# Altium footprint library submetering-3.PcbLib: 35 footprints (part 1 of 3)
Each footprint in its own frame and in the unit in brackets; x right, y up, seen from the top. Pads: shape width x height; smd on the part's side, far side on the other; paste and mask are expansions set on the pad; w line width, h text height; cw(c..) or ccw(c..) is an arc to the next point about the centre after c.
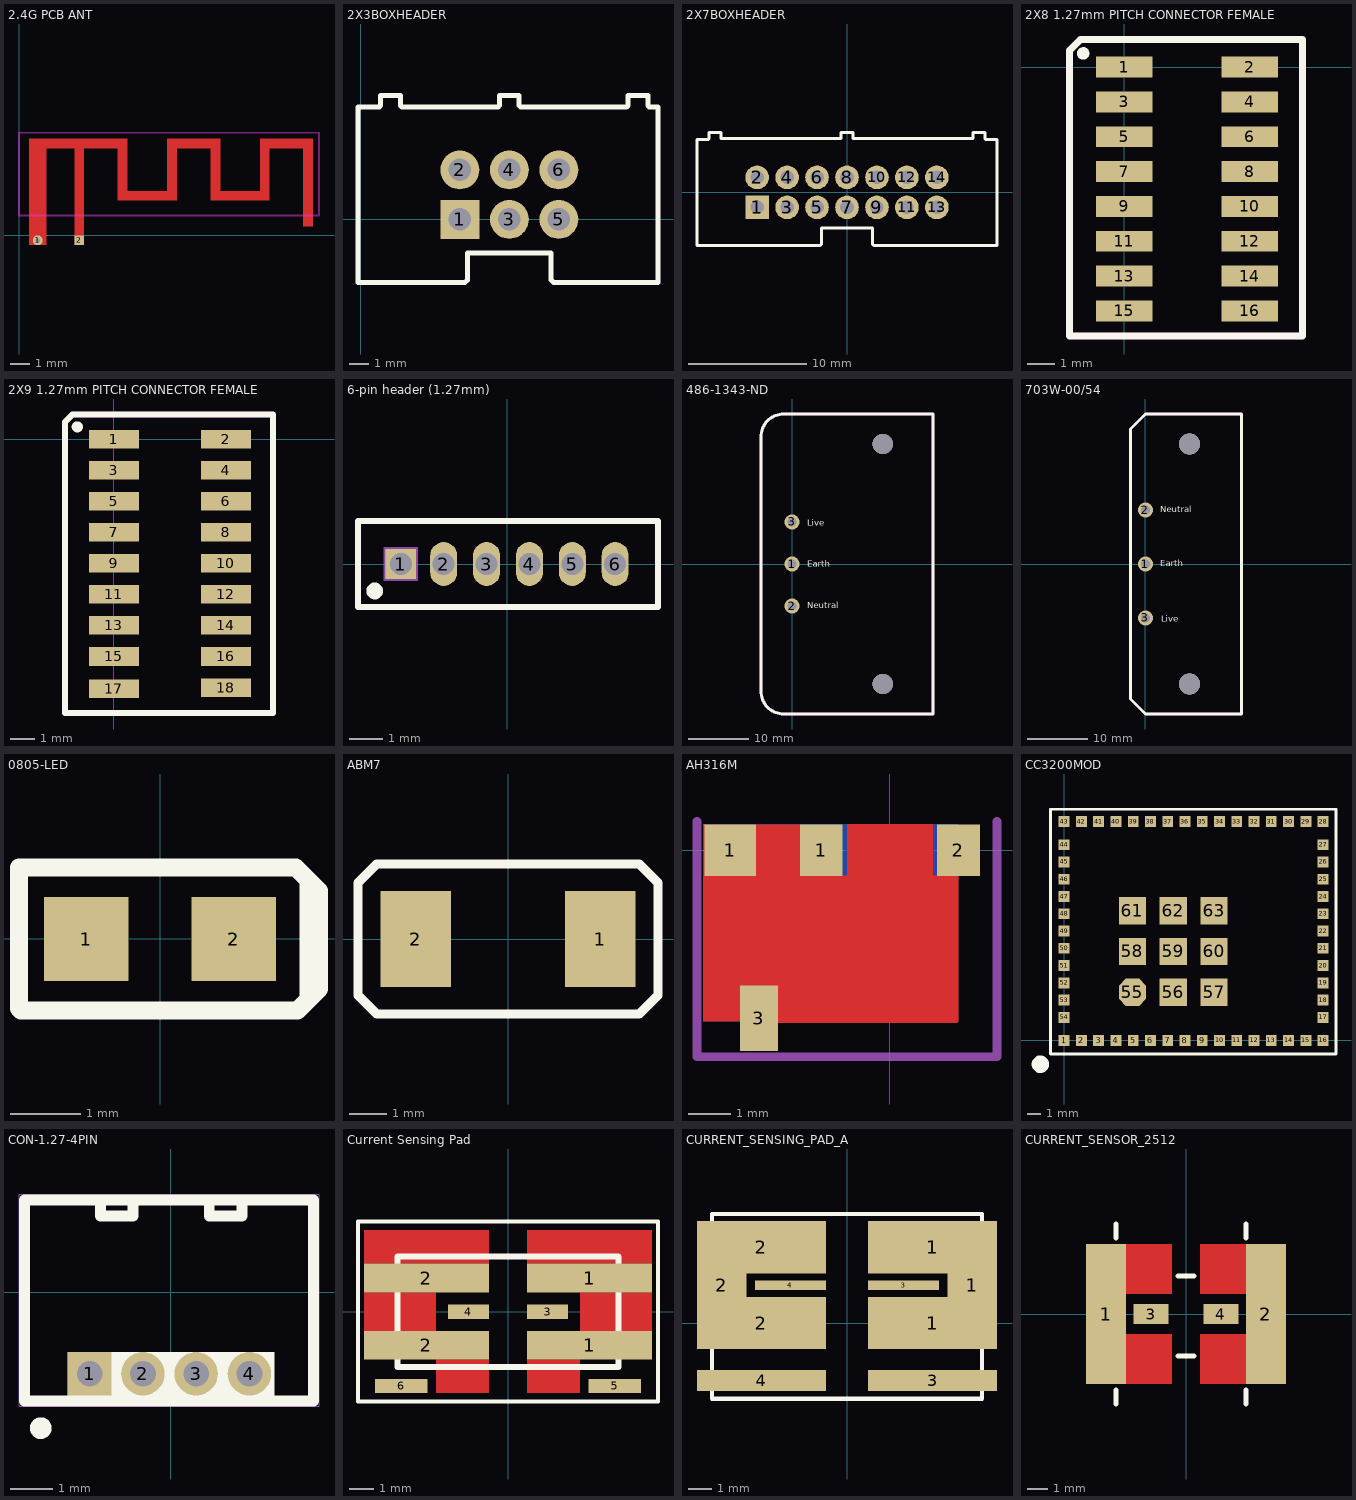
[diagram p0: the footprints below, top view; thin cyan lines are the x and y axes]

## 2.4G PCB ANT [mm] "2.4G PCb Single Ended Antenna"
pads (2):
  round 0.5 hole 0.25 paste+0 mask+0: 1(0.95,-0.25)
  rect 0.5x0.5 smd paste+0 mask+0: 2(3.05,-0.25)
TopLayer:
  rectangle: 14.4,0.46 14.9,4.4
  rectangle: 12.2,4.4 14.9,4.9
  rectangle: 12.2,1.76 12.7,4.4
  rectangle: 10.2,1.76 12.2,2.26
  rectangle: 9.7,1.76 10.2,4.4
  rectangle: 7.5,4.4 10.2,4.9
  rectangle: 7.5,1.76 8,4.4
  rectangle: 5.5,1.76 7.5,2.26
  rectangle: 5,1.76 5.5,4.4
  rectangle: 2.8,-0.5 3.3,4.4
  rectangle: 0.5,-0.5 1.4,4.4
  rectangle: 0.5,4.4 5.5,4.9
KeepOutLayer:
  lines w0.1: 0,1 15.2,1 15.2,5.2 0,5.2 0,1

## 2X3BOXHEADER [mm]
pads (6):
  rect 2x2 hole 1.15: 1(5.08,0)
  round 2 hole 1.15: 2(5.08,2.54) 3(7.62,0) 4(7.62,2.54) 5(10.16,0) 6(10.16,2.54)
TopOverlay:
  lines w0.254: -0.15,-3.23 5.352,-3.23 5.47,-3.112 5.47,-1.73 9.77,-1.73 9.77,-3.112 9.888,-3.23 15.255,-3.23 15.255,5.77 14.804,5.77 14.732,5.842 14.732,6.35 13.716,6.35 13.716,5.842 13.644,5.77 8.2,5.77 8.128,5.842 8.128,6.35 7.112,6.35 7.112,5.842 7.04,5.77 2.104,5.77 2.032,5.842 2.032,6.35 1.016,6.35 1.016,5.842 0.944,5.77 -0.15,5.77 -0.15,-3.23

## 2X7BOXHEADER [mm]
pads (14):
  rect 2x2 hole 1.15: 1(-7.62,-1.27)
  round 2 hole 1.15: 2(-7.62,1.27) 3(-5.08,-1.27) 4(-5.08,1.27) 5(-2.54,-1.27) 6(-2.54,1.27) 7(0,-1.27) 8(0,1.27) 9(2.54,-1.27) 10(2.54,1.27) 11(5.08,-1.27) 12(5.08,1.27) 13(7.62,-1.27) 14(7.62,1.27)
TopOverlay:
  lines w0.254: -12.715,-4.5 -2.268,-4.5 -2.15,-4.382 -2.15,-3 2.15,-3 2.15,-4.382 2.268,-4.5 12.715,-4.5 12.715,4.5 11.756,4.5 11.684,4.572 11.684,5.08 10.668,5.08 10.668,4.572 0.508,4.572 0.508,5.08 -0.508,5.08 -0.508,4.572 -10.668,4.572 -10.668,5.08 -11.684,5.08 -11.684,4.572 -11.756,4.5 -12.715,4.5 -12.715,-4.5

## 2X8 1.27mm PITCH CONNECTOR FEMALE [mm] "2X8 1.27mm PITCH CONNECTOR FEMALE"
pads (16):
  rect 2.05x0.76 smd: 1(0,0) 2(4.575,0) 3(0,-1.27) 4(4.575,-1.27) 5(0,-2.54) 6(4.575,-2.54) 7(0,-3.81) 8(4.575,-3.81) 9(0,-5.08) 10(4.575,-5.08) 11(0,-6.35) 12(4.575,-6.35) 13(0,-7.62) 14(4.575,-7.62) 15(0,-8.89) 16(4.575,-8.89)
TopOverlay:
  circle w0.254: c-1.5,0.5 r0.1
TopOverlay keep-out:
  lines w0.254: -2,-9.8 6.5,-9.8 6.5,1 -1.6,1 -2,0.6 -2,-9.8

## 2X9 1.27mm PITCH CONNECTOR FEMALE [mm] "2X9 1.27mm PITCH CONNECTOR FEMALE"
pads (18):
  rect 2.05x0.76 smd: 1(0,0) 2(4.575,0) 3(0,-1.27) 4(4.575,-1.27) 5(0,-2.54) 6(4.575,-2.54) 7(0,-3.81) 8(4.575,-3.81) 9(0,-5.08) 10(4.575,-5.08) 11(0,-6.35) 12(4.575,-6.35) 13(0,-7.62) 14(4.575,-7.62) 15(0,-8.89) 16(4.575,-8.89) 17(0,-10.216) 18(4.575,-10.16)
TopOverlay:
  circle w0.254: c-1.5,0.5 r0.1
TopOverlay keep-out:
  lines w0.254: -2,-11.2 6.5,-11.2 6.5,1 -1.7,1 -2,0.7 -2,-11.2

## 6-pin header (1.27mm) [mm] "6 pin header 1.27mm"
pads (6):
  rect 0.9x0.9 hole 0.65 mask+0: 1(-3.15,0)
  oval 0.8x1.3 hole 0.65 mask+0: 2(-1.88,0) 3(-0.61,0) 4(0.66,0) 5(1.93,0) 6(3.2,0)
TopOverlay:
  circle w0.25: c-3.925,-0.8 r0.125
  lines w0.178: -4.42,-1.27 4.47,-1.27 4.47,1.27 -4.42,1.27 -4.42,-1.27
Mechanical5:
  rectangle: -3.658,-0.508 -2.642,0.508
  lines w0.127: -4.42,-1.27 -4.42,-0.635 -4.42,0.635 -4.42,1.27 4.47,1.27 4.47,-1.27 -4.42,-1.27

## 486-1343-ND [mm]
pads (3):
  round 2.54 hole 1.5: 1(0,0) 2(0,-7) 3(0,7)
via 15.1,20 diameter 3.4 hole 3.4
via 15.1,-20 diameter 3.4 hole 3.4
TopOverlay:
  text "Earth" at 2.5,-0.5 h1.02
  text "Neutral" at 2.5,-7.4 h1.02
  text "Live" at 2.5,6.4 h1.02
TopOverlay keep-out:
  lines w0.5: -5.2,-21.2 -5.2,21.215 ; -5.185,-21.215 ccw(c-1.4,-21.215) -1.4,-25 ; -5.185,21.215 cw(c-1.4,21.215) -1.4,25 ; -1.573,-25 23.5,-25 23.5,25 -1.3,25

## 703W-00/54 [mm] "IEC 320-C14 , Receptacle, Male Pins"
pads (3):
  round 2.54 hole 1.5: 1(0,0) 2(0,9) 3(0,-9)
via 7.3,-20 diameter 3.5 hole 3.5
via 7.3,20 diameter 3.5 hole 3.5
TopOverlay:
  text "Live" at 2.6,-9.6 h1.02
  text "Earth" at 2.5,-0.4 h1.02
  text "Neutral" at 2.5,8.6 h1.02
TopOverlay keep-out:
  lines w0.5: -2.5,-22.5 -2.5,22.5 0,25 16,25 16,-25 0,-25 -2.5,-22.5

## 0805-LED [mm]
pads (2):
  rect 1.2x1.2 smd: 1(-1.055,-0.005) 2(1.045,-0.005)
TopOverlay:
  lines w0.254: 2.102,-0.869 2.102,0.835 ; -2.011,-0.995 -2.011,1.011 1.926,1.011 2.256,0.681 2.256,-0.716 1.951,-1.021 -1.986,-1.021 -2.011,-0.995

## ABM7 [mm]
pads (2):
  rect 1.9x2.6 smd: 1(2.5,0) 2(-2.5,0)
TopOverlay:
  lines w0.254: -4.064,-1.524 -4.064,1.524 -3.556,2.032 3.556,2.032 4.064,1.524 4.064,-1.524 3.556,-2.032 -3.556,-2.032 -4.064,-1.524

## AH316M [mm]
pads (4):
  rect 1.2x1.2 smd paste+0 mask+0: 1(-3.725,0)
  rect 1x1.2 smd: 1(-1.6,0) 2(1.6,0)
  rect 0.889x1.524 smd paste+0 mask+0: 3(-3.056,-3.925)
TopLayer:
  rectangle: -4.35,-0.6 -2,0.6
  rectangle: -3.5,-4.5 -2.611,-0.3
  pour cut-out: -4.35,-0.6 -3.5,-0.6 -3.501,-4 -4.35,-4
  pour cut-out: -1,0.6 1,0.6 1,-0.6 -1,-0.6
  pour cut-out: -2.625,-0.6 1.6,-0.6 1.6,-4 1.575,-4.025 -2.625,-4.025
BottomLayer:
  pour cut-out: 1.6,0.6 1.6,-4 -4.35,-4 -4.35,0.6
Mechanical1:
  lines w0.2: -4.5,0.675 -4.5,-4.825 2.5,-4.825 2.5,0.675

## CC3200MOD [mm]
pads (63):
  rect 0.8x0.8 smd: 1(0,0) 2(1.27,0) 3(2.54,0) 4(3.81,0) 5(5.08,0) 6(6.35,0) 7(7.62,0) 8(8.89,0) 9(10.16,0) 10(11.43,0) 11(12.7,0) 12(13.97,0) 13(15.24,0) 14(16.51,0) 15(17.78,0) 16(19.05,0) 17(19.05,1.7) 18(19.05,2.97) 19(19.05,4.24) 20(19.05,5.51) 21(19.05,6.78) 22(19.05,8.05) 23(19.05,9.32) 24(19.05,10.59) 25(19.05,11.86) 26(19.05,13.13) 27(19.05,14.4) 28(19.05,16.1) 29(17.78,16.1) 30(16.51,16.1) 31(15.24,16.1) 32(13.97,16.1) 33(12.7,16.1) 34(11.43,16.1) 35(10.16,16.1) 36(8.89,16.1) 37(7.62,16.1) 38(6.35,16.1) 39(5.08,16.1) 40(3.81,16.1) 41(2.54,16.1) 42(1.27,16.1) 43(0,16.1) 44(0,14.4) 45(0,13.13) 46(0,11.86) 47(0,10.59) 48(0,9.32) 49(0,8.05) 50(0,6.78) 51(0,5.51) 52(0,4.24) 53(0,2.97) 54(0,1.7)
  oct 2x2 smd: 55(5.025,3.55)
  rect 2x2 smd: 56(8.025,3.55) 57(11.025,3.55) 58(5.025,6.55) 59(8.025,6.55) 60(11.025,6.55) 61(5.025,9.55) 62(8.025,9.55) 63(11.025,9.55)
TopOverlay:
  circle w0.64: c-1.75,-1.75 r0.32
  lines w0.2: -1,-1 -1,15.165 -1,17 20,17 20,-1 -1,-1

## CON-1.27-4PIN [mil] "1.27mm connector 4 pin"
pads (4):
  rect 40x40 hole 23.62: 1(-74.74,-74.78)
  round 40 hole 23.62: 2(-25.74,-74.78) 3(23.26,-74.78) 4(72.26,-74.78)
TopOverlay:
  circle w10: c-119.74,-124.78 r5
  region: -94.74,-54.78 95.26,-54.78 95.26,-94.78 -94.74,-94.78
  lines w10: -134.74,-99.78 -134.74,85.22 131.26,85.22 131.26,-99.78 -134.74,-99.78 ; -64.74,70.22 -64.74,85.22 -34.74,85.22 -34.74,70.22 -64.74,70.22 ; 35.26,70.22 35.26,85.22 65.26,85.22 65.26,70.22 35.26,70.22
BottomOverlay:
  region: -94.74,-54.78 95.26,-54.78 95.26,-94.78 -94.74,-94.78
Mechanical 17:
  lines w1: -139.74,-104.78 -139.74,90.22 136.26,90.22 136.26,-104.78 -139.74,-104.78
Mechanical 18:
  lines w1: -139.74,-104.78 -139.74,90.22 136.26,90.22 136.26,-104.78 -139.74,-104.78

## Current Sensing Pad [mm] "Current Sensing Pad for 2512"
pads (8):
  rect 5.2x1.2 smd: 1(3.4,-1.4) 1(3.4,1.4) 2(-3.4,-1.4) 2(-3.4,1.4)
  rect 1.7x0.6 smd: 3(1.65,0) 4(-1.65,0)
  rect 2.2x0.6 smd: 5(4.45,-3.1) 6(-4.45,-3.1)
TopLayer:
  rectangle: 0.8,-3.4 3,-2
  rectangle: -3,-3.4 -0.8,-2
  rectangle: 3,-0.8 6,0.8
  rectangle: -6,-0.8 -3,0.8
  rectangle: -6,2 -0.8,3.4
  rectangle: 0.8,2 6,3.4
TopOverlay:
  lines w0.178: -6.25,-3.75 -6.25,3.75 6.25,3.75 6.25,-3.75 -6.25,-3.75
  lines w0.254: -4.6,-2.3 4.6,-2.3 4.6,-1.5 4.6,-0.3 4.6,0.5 4.6,1.025 4.6,2.075 4.6,2.3 -4.6,2.3 -4.6,-2.3
Mechanical5:
  text ".Designator" at 0,0 h1.02

## CURRENT_SENSING_PAD_A [mm]
pads (10):
  rect 5.44x2.2 smd: 1(3.615,0) 2(-3.615,0)
  rect 5.44x2.2 smd mask+0.102: 1(3.615,3.2) 2(-3.615,3.2)
  rect 2.1x1.1 smd paste+0: 1(5.285,1.6) 2(-5.285,1.6)
  rect 3x0.4 smd: 3(2.395,1.6) 4(-2.395,1.6)
  rect 5.44x0.89 smd: 3(3.615,-2.435) 4(-3.615,-2.435)
TopOverlay:
  lines w0.178: -5.7,-3.2 -5.7,4.6 5.7,4.6 5.7,-3.2 -5.7,-3.2

## CURRENT_SENSOR_2512 [mm] "2512 Current Sensor"
pads (4):
  rect 2x7 smd: 1(-4,0) 2(4,0)
  rect 1.75x1 smd: 3(-1.75,0) 4(1.75,0)
TopLayer:
  rectangle: -3,1 -0.7,3.5
  rectangle: 0.7,1 3,3.5
  rectangle: -3,-3.5 -0.7,-1
  rectangle: 0.7,-3.5 3,-1
TopOverlay:
  lines w0.254: -3.5,-4.5 -3.5,-3.8 ; -3.5,3.8 -3.5,4.5 ; -0.4,-2.1 0.4,-2.1 ; -0.4,1.9 0.4,1.9 ; 3,-4.5 3,-3.8 ; 3,3.8 3,4.5
Mechanical5:
  text ".Designator" at 0,0 h1.02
